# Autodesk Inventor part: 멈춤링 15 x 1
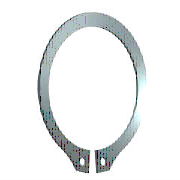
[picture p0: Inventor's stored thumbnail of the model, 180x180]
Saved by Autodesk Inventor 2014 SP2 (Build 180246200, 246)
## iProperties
Created: 2012-02
Part Number: 멈춤링 15 x 1
Material: 강철, 연강
Description: 리테이닝 링(C형)
Document SubType Name: Modeling
Standard: KS B 1336
Designer: mduedu
Standards Organization: KS
Language: ko-KR
Size Designation: 15 x 1
Categories: <MemberInstance><Categories><Category DisplayName="샤프트 부품" InternalName="7f7aeb1f-a693-4053-b835-cee3144e0d98" Mnemonic="SHFT"><Category DisplayName="써클립" Inter
Density: 1 g/cm^3
Appearance: 파란색 - 벽 페인트 - 광택
IsCustomPart: 1
Author: mduedu
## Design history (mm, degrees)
sketch "스케치1"
  geometry: L1 (-6, 0)-(6, 0) reference; L2 (0, 20.189)-(0, -80.536) reference; L3 (-48.09, 0)-(48.09, 0) reference; L4 (-0.425, -14.637)-(-0.425, -18.137); L5 (-0.425, -6.54)-(-0.425, -13.29); L6 (-2.795, 2.1)-(3.672, 2.1); L7 (0.425, -6.54)-(0.425, -13.29); L8 (0.425, -14.637)-(0.425, -18.137); C1 r 0.85 at (-1.7, -16.283); C2 r 0.85 at (1.7, -16.283); A1 r 7.15 centre (0, -7.5) between (0.425, -14.637) and (-0.425, -14.637); A2 r 9.075 centre (0, -6.975) between (4.291, -14.971) and (-4.291, -14.971); A3 r 10.646 centre (0, -7.5) between (-2.023, -17.952) and (-0.425, -18.137); A4 r 1.7 centre (-1.7, -16.283) between (-3.397, -16.376) and (-2.023, -17.952); A5 r 1.7 centre (-5.095, -16.469) between (-3.397, -16.376) and (-4.291, -14.971); A6 r 1.7 centre (5.095, -16.469) between (4.291, -14.971) and (3.397, -16.376); A7 r 1.7 centre (1.7, -16.283) between (2.023, -17.952) and (3.397, -16.376); A8 r 10.646 centre (0, -7.5) between (0.425, -18.137) and (2.023, -17.952)
  constraints: 16 point on circle, 12 end point, 10 centre point, 9 symmetric about line, 5 point on line, 4 tangent, 3 coincident, 2 horizontal, 1 perpendicular, 1 vertical, 5 other
  dimensions: "d0" = 14.3 diameter of A1 (= ND); "d1" = 3.5 distance of L4.end L4.start (= SRB2); "d6" = 0.425 distance between parallel lines of L2 L5 (= 0.25 x SD5); "d7" = 2.1 distance between parallel lines of L6 L3 (= SRB1); "d8" = 0.525 distance of A1.centre A2.centre (= 0.25 x SRB1); "d9" = 1.7 radius of A4 (= SD5); "d10" = 1.7 radius of A5 (= SD5); "d11" = 1.275 distance from line of L4 A4.centre (= 0.75 x SD5); "d12" = 1.7 diameter of C1 (= SD5); "d13" = 1.7 diameter of C2 (= SD5); "d14" = 7.5 distance from line of A1.centre L1 (= 0.5 x WD)
extrude "본체" new body sketch "스케치1" distance "d2" = 1 (= SD); taper "d3" = 0 deg
workaxis "Work Axis1"
workplane "Work Plane1"
body "Solid1"
other parameters: "WD" = 15 (= WDMIN) [user parameter; used in 1 equation term], "SD" = 1 [user parameter; used in 1 equation term], "SRB1" = 2.1 [user parameter; used in 2 equation terms], "ND" = 14.3 [user parameter; used in 1 equation term], "SRB2" = 3.5 [user parameter; used in 1 equation term], "SD5" = 1.7 [user parameter; used in 6 equation terms], "d15" = 0, "d16" = 0, "d17" = 0, "d41" = 0, "d42" = 0, "WDMIN" = 15 [user parameter; used in 1 equation term], "SD3" = 13.8 [user parameter], "WDMAX" = 16 [user parameter]
